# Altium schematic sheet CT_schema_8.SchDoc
size 380 x 278 mm
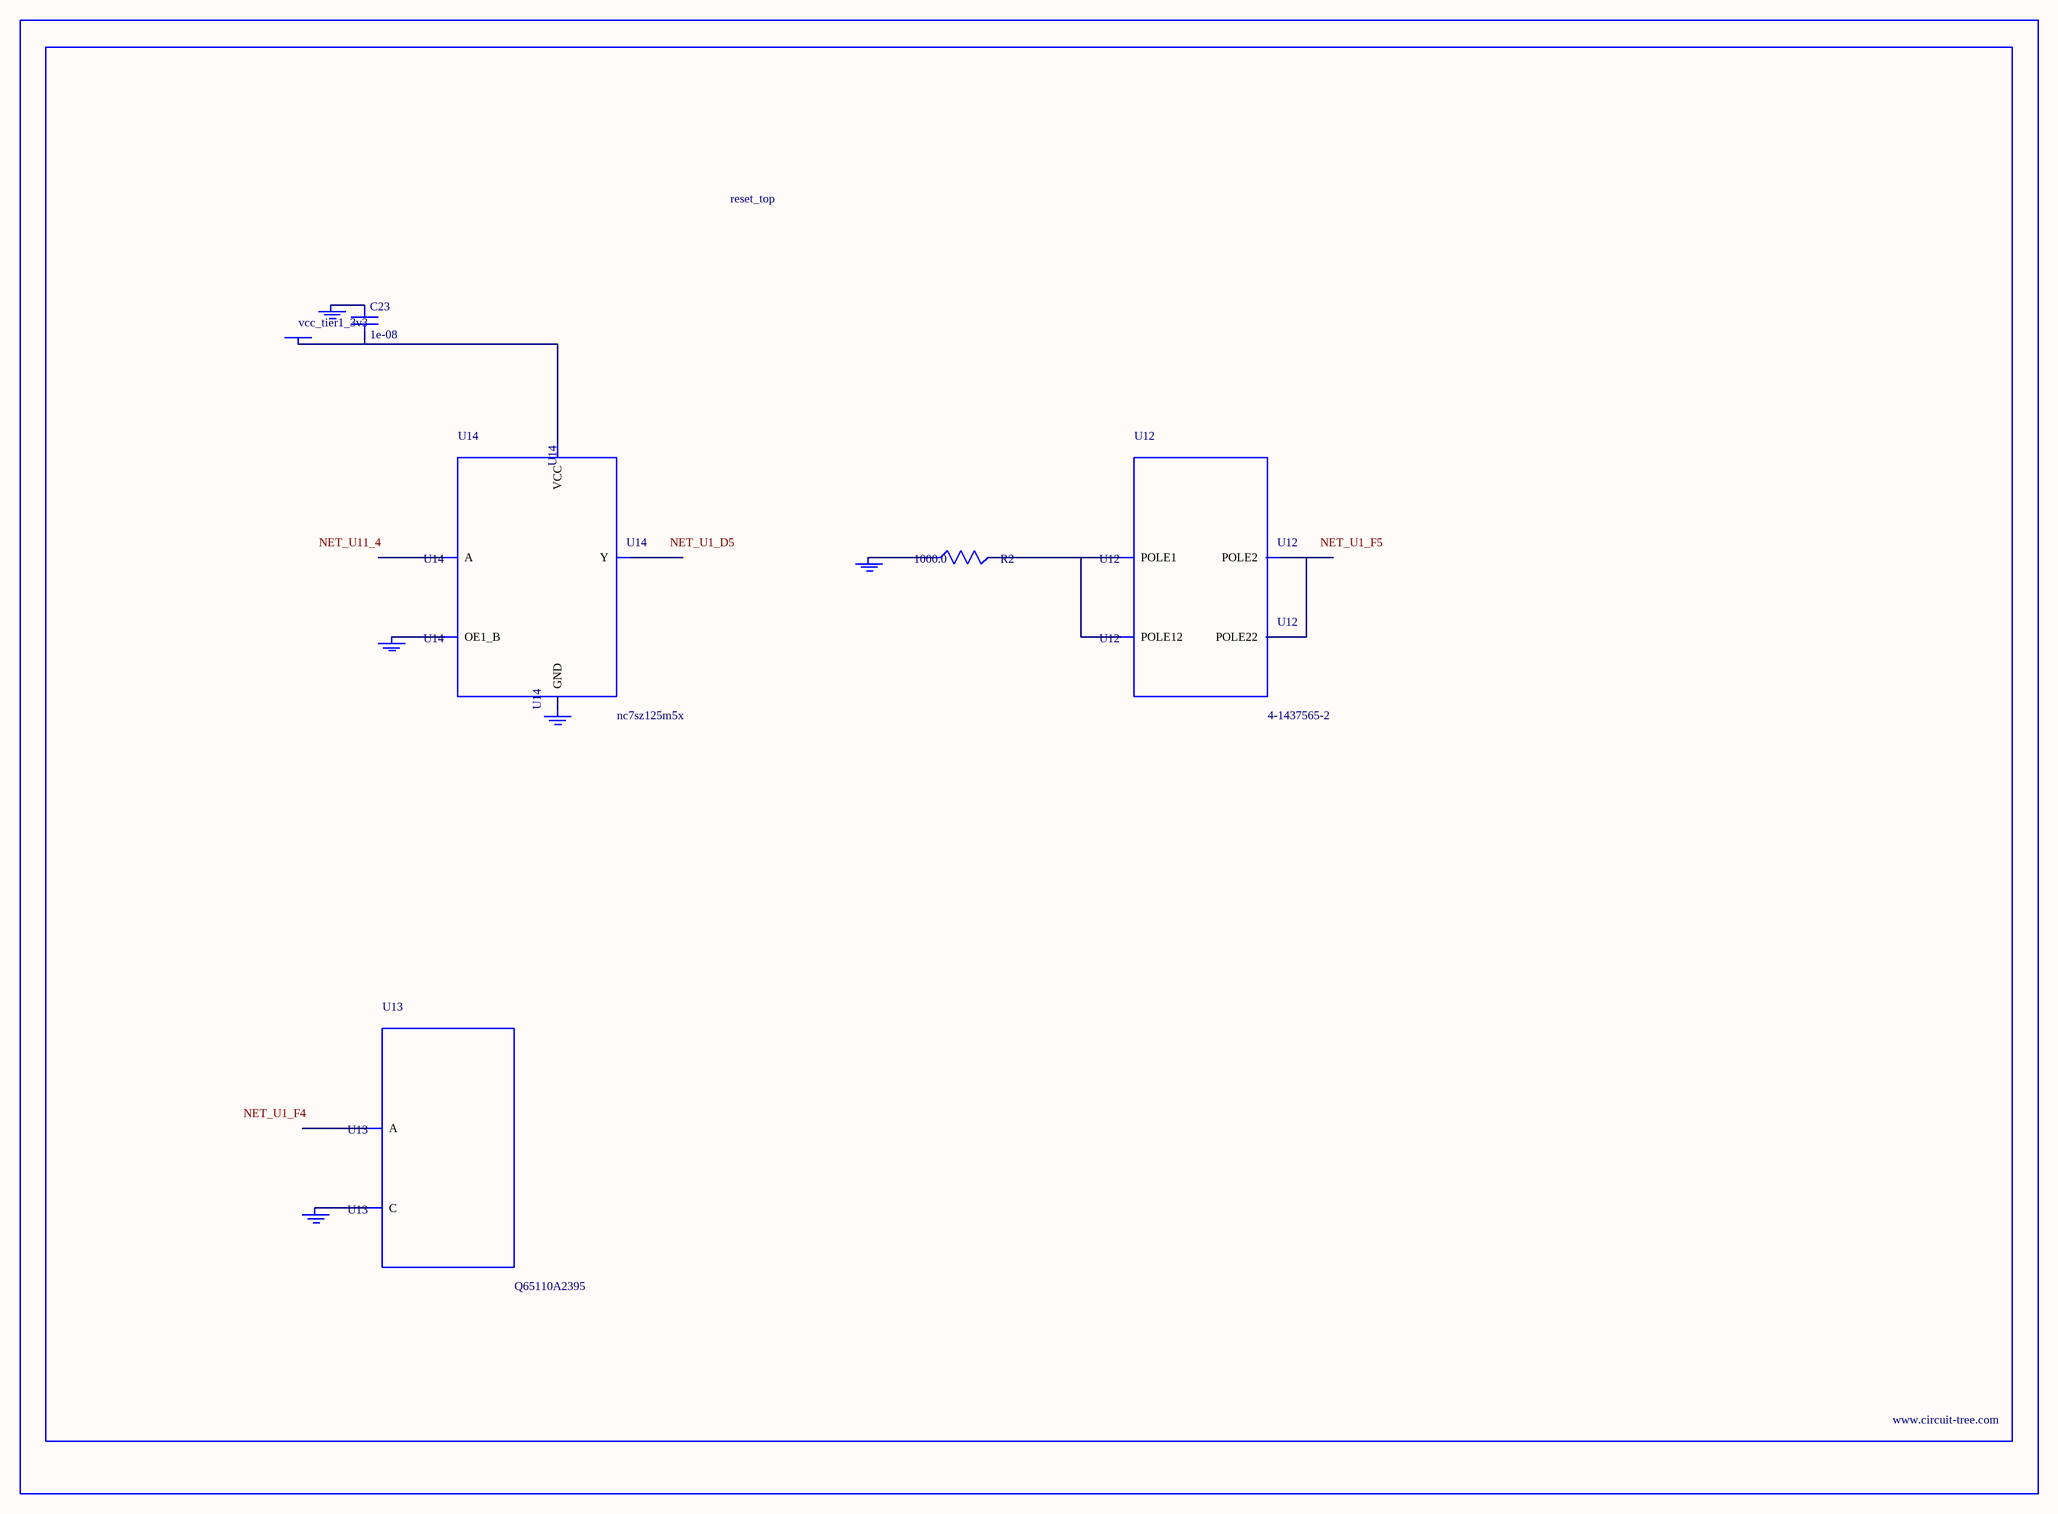
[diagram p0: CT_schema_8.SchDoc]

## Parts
BORDER7  (no value)
C23  1e-08  [C0402]
GND_INSTANCE_7_0  (no value)
GND_INSTANCE_7_1  (no value)
GND_INSTANCE_7_2  (no value)
GND_INSTANCE_7_3  (no value)
GND_INSTANCE_7_4  (no value)
POWER_INSTANCE_7_0  vcc_tier1_3v3
R2  1000.0  [R0603]
U12  4-1437565-2  [SW_4-1437565-2]
U13  Q65110A2395  [LGM67K-G1J2-24-Z]
U14  nc7sz125m5x  [NC7SZ125M5X]

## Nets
NetC23_1: C23.1 GND_INSTANCE_7_2.0(GND)
NetC23_2: C23.2 POWER_INSTANCE_7_0.0(PWR) U14.5(VCC)
NetGND_INSTANCE_7_0_0: GND_INSTANCE_7_0.0(GND) R2.1
NetGND_INSTANCE_7_1_0: GND_INSTANCE_7_1.0(GND) U13.C
NetGND_INSTANCE_7_3_0: GND_INSTANCE_7_3.0(GND) U14.1(OE1_B)
NetGND_INSTANCE_7_4_0: GND_INSTANCE_7_4.0(GND) U14.3(GND)
NetR2_2: R2.2 U12.1(POLE1) U12.2(POLE12)
NetU12_3: U12.3(POLE2) U12.4(POLE22)

Not connected (* = marked no-connect by the designer): U13 A; U14 2(A) 4(Y)

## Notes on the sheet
- Labels drawn without touching a wire or pin: NET_U1_D5, NET_U1_F4, NET_U1_F5, NET_U11_4

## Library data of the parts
BORDER7 = BORDER_PAGE7
C23 = C0402C103K3RAC
GND_INSTANCE_7_0-GND_INSTANCE_7_4 = GND
POWER_INSTANCE_7_0 = PWR
R2 = RC0603JR-071KL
